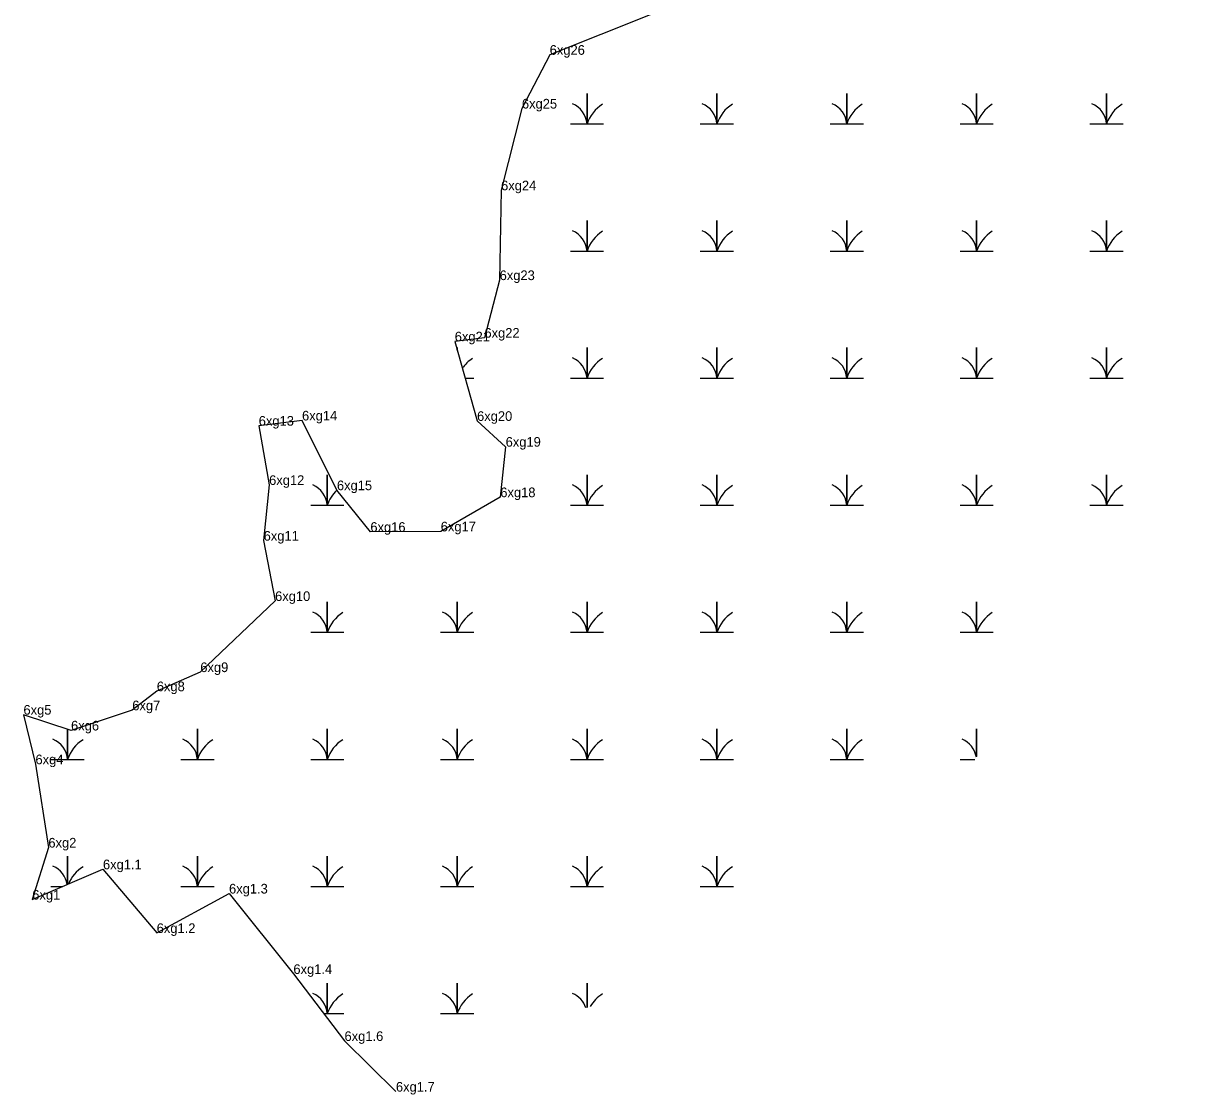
# Model space of a CAD drawing. Extents: x 2072529 to 2268796, y 436423 to 470406.
# Drawn here: x 2152740 to 2153347, y 437861 to 438415 of the extents above; entities that cross this region are included whole.
import ezdxf

# ---------------------------------------------------------------- set-up
doc = ezdxf.new("R2010")
doc.units = 0
for name, color, linetype in [('Exist Environmental Wetland Boundary Cogo Comment', 7, 'Continuous'), ('Exist Environmental Wetland Boundary Cogo Point CELL', 7, 'Continuous'), ('Old_Level_20', 7, 'Continuous')]:
    doc.layers.add(name, color=color, linetype=linetype)

msp = doc.modelspace()

# ---------------------------------------------------------------- linework, layer by layer
at = {"layer": 'Exist Environmental Wetland Boundary Cogo Point CELL'}
for points in [[(2153023.06, 438363.23), (2153031.66, 438363.23), (2153031.66, 438379.01), (2153031.66, 438363.23), (2153040.26, 438363.23)], [(2153090.31, 438363.23), (2153098.91, 438363.23), (2153098.91, 438379.01), (2153098.91, 438363.23), (2153107.51, 438363.23)], [(2153157.56, 438363.23), (2153166.16, 438363.23), (2153166.16, 438379.01), (2153166.16, 438363.23), (2153174.76, 438363.23)], [(2153224.81, 438363.23), (2153233.41, 438363.23), (2153233.41, 438379.01), (2153233.41, 438363.23), (2153242.01, 438363.23)], [(2153292.06, 438363.23), (2153300.66, 438363.23), (2153300.66, 438379.01), (2153300.66, 438363.23), (2153309.26, 438363.23)], [(2153023.06, 438297.43), (2153031.66, 438297.43), (2153031.66, 438313.21), (2153031.66, 438297.43), (2153040.26, 438297.43)], [(2153090.31, 438297.43), (2153098.91, 438297.43), (2153098.91, 438313.21), (2153098.91, 438297.43), (2153107.51, 438297.43)], [(2153157.56, 438297.43), (2153166.16, 438297.43), (2153166.16, 438313.21), (2153166.16, 438297.43), (2153174.76, 438297.43)], [(2153224.81, 438297.43), (2153233.41, 438297.43), (2153233.41, 438313.21), (2153233.41, 438297.43), (2153242.01, 438297.43)], [(2153292.06, 438297.43), (2153300.66, 438297.43), (2153300.66, 438313.21), (2153300.66, 438297.43), (2153309.26, 438297.43)], [(2152964.41, 438246.19), (2152964.41, 438247.41), (2152964.41, 438246.19)], [(2153023.06, 438231.63), (2153031.66, 438231.63), (2153031.66, 438247.41), (2153031.66, 438231.63), (2153040.26, 438231.63)], [(2153090.31, 438231.63), (2153098.91, 438231.63), (2153098.91, 438247.41), (2153098.91, 438231.63), (2153107.51, 438231.63)], [(2153157.56, 438231.63), (2153166.16, 438231.63), (2153166.16, 438247.41), (2153166.16, 438231.63), (2153174.76, 438231.63)], [(2153224.81, 438231.63), (2153233.41, 438231.63), (2153233.41, 438247.41), (2153233.41, 438231.63), (2153242.01, 438231.63)], [(2153292.06, 438231.63), (2153300.66, 438231.63), (2153300.66, 438247.41), (2153300.66, 438231.63), (2153309.26, 438231.63)], [(2152968.5, 438231.63), (2152973.01, 438231.63)], [(2152888.56, 438165.83), (2152897.16, 438165.83), (2152897.16, 438181.61), (2152897.16, 438165.83), (2152905.76, 438165.83)], [(2153023.06, 438165.83), (2153031.66, 438165.83), (2153031.66, 438181.61), (2153031.66, 438165.83), (2153040.26, 438165.83)], [(2153090.31, 438165.83), (2153098.91, 438165.83), (2153098.91, 438181.61), (2153098.91, 438165.83), (2153107.51, 438165.83)], [(2153157.56, 438165.83), (2153166.16, 438165.83), (2153166.16, 438181.61), (2153166.16, 438165.83), (2153174.76, 438165.83)], [(2153224.81, 438165.83), (2153233.41, 438165.83), (2153233.41, 438181.61), (2153233.41, 438165.83), (2153242.01, 438165.83)], [(2153292.06, 438165.83), (2153300.66, 438165.83), (2153300.66, 438181.61), (2153300.66, 438165.83), (2153309.26, 438165.83)], [(2152888.56, 438100.03), (2152897.16, 438100.03), (2152897.16, 438115.81), (2152897.16, 438100.03), (2152905.76, 438100.03)], [(2152955.81, 438100.03), (2152964.41, 438100.03), (2152964.41, 438115.81), (2152964.41, 438100.03), (2152973.01, 438100.03)], [(2153023.06, 438100.03), (2153031.66, 438100.03), (2153031.66, 438115.81), (2153031.66, 438100.03), (2153040.26, 438100.03)], [(2153090.31, 438100.03), (2153098.91, 438100.03), (2153098.91, 438115.81), (2153098.91, 438100.03), (2153107.51, 438100.03)], [(2153157.56, 438100.03), (2153166.16, 438100.03), (2153166.16, 438115.81), (2153166.16, 438100.03), (2153174.76, 438100.03)], [(2153224.81, 438100.03), (2153233.41, 438100.03), (2153233.41, 438115.81), (2153233.41, 438100.03), (2153242.01, 438100.03)], [(2152754.06, 438034.23), (2152762.66, 438034.23), (2152762.66, 438049.82)], [(2152762.66, 438049.82), (2152762.66, 438034.23), (2152771.26, 438034.23)], [(2152821.31, 438034.23), (2152829.91, 438034.23), (2152829.91, 438050.01), (2152829.91, 438034.23), (2152838.51, 438034.23)], [(2152888.56, 438034.23), (2152897.16, 438034.23), (2152897.16, 438050.01), (2152897.16, 438034.23), (2152905.76, 438034.23)], [(2152955.81, 438034.23), (2152964.41, 438034.23), (2152964.41, 438050.01), (2152964.41, 438034.23), (2152973.01, 438034.23)], [(2153023.06, 438034.23), (2153031.66, 438034.23), (2153031.66, 438050.01), (2153031.66, 438034.23), (2153040.26, 438034.23)], [(2153090.31, 438034.23), (2153098.91, 438034.23), (2153098.91, 438050.01), (2153098.91, 438034.23), (2153107.51, 438034.23)], [(2153157.56, 438034.23), (2153166.16, 438034.23), (2153166.16, 438050.01), (2153166.16, 438034.23), (2153174.76, 438034.23)], [(2153233.41, 438035.69), (2153233.41, 438050.01), (2153233.41, 438035.69)], [(2153224.81, 438034.23), (2153232.4, 438034.23)], [(2152762.66, 437969.48), (2152762.66, 437984.21), (2152762.66, 437969.48)], [(2152821.31, 437968.43), (2152829.91, 437968.43), (2152829.91, 437984.21), (2152829.91, 437968.43), (2152838.51, 437968.43)], [(2152888.56, 437968.43), (2152897.16, 437968.43), (2152897.16, 437984.21), (2152897.16, 437968.43), (2152905.76, 437968.43)], [(2152955.81, 437968.43), (2152964.41, 437968.43), (2152964.41, 437984.21), (2152964.41, 437968.43), (2152973.01, 437968.43)], [(2153023.06, 437968.43), (2153031.66, 437968.43), (2153031.66, 437984.21), (2153031.66, 437968.43), (2153040.26, 437968.43)], [(2153090.31, 437968.43), (2153098.91, 437968.43), (2153098.91, 437984.21), (2153098.91, 437968.43), (2153107.51, 437968.43)], [(2152754.06, 437968.43), (2152760.19, 437968.43)], [(2152895.28, 437902.63), (2152897.16, 437902.63), (2152897.16, 437918.41), (2152897.16, 437902.63), (2152905.76, 437902.63)], [(2152955.81, 437902.63), (2152964.41, 437902.63), (2152964.41, 437918.41), (2152964.41, 437902.63), (2152973.01, 437902.63)], [(2153031.66, 437905.77), (2153031.66, 437918.41), (2153031.66, 437905.77)]]:
    msp.add_lwpolyline(points, dxfattribs=at)
for centre, radius, start, end in [((2153019.4, 438362.34), 12.3, 4.14034, 67.53497), ((2153086.65, 438362.34), 12.3, 4.14034, 67.53497), ((2153153.9, 438362.34), 12.3, 4.14034, 67.53497), ((2153221.15, 438362.34), 12.3, 4.14034, 67.53497), ((2153288.4, 438362.34), 12.3, 4.14034, 67.53497), ((2153049.9, 438357.16), 19.22, 122.12745, 161.62219), ((2153117.15, 438357.16), 19.22, 122.12745, 161.62219), ((2153184.4, 438357.16), 19.22, 122.12745, 161.62219), ((2153251.65, 438357.16), 19.22, 122.12745, 161.62219), ((2153318.9, 438357.16), 19.22, 122.12745, 161.62219), ((2153019.4, 438296.54), 12.3, 4.14034, 67.53497), ((2153049.9, 438291.36), 19.22, 122.12745, 161.62219), ((2153086.65, 438296.54), 12.3, 4.14034, 67.53497), ((2153117.15, 438291.36), 19.22, 122.12745, 161.62219), ((2153153.9, 438296.54), 12.3, 4.14034, 67.53497), ((2153184.4, 438291.36), 19.22, 122.12745, 161.62219), ((2153221.15, 438296.54), 12.3, 4.14034, 67.53497), ((2153251.65, 438291.36), 19.22, 122.12745, 161.62219), ((2153288.4, 438296.54), 12.3, 4.14034, 67.53497), ((2153318.9, 438291.36), 19.22, 122.12745, 161.62219), ((2152982.65, 438225.56), 19.22, 122.12745, 144.2598), ((2153019.4, 438230.74), 12.3, 4.14034, 67.53497), ((2153049.9, 438225.56), 19.22, 122.12745, 161.62219), ((2153086.65, 438230.74), 12.3, 4.14034, 67.53497), ((2153117.15, 438225.56), 19.22, 122.12745, 161.62219), ((2153153.9, 438230.74), 12.3, 4.14034, 67.53497), ((2153184.4, 438225.56), 19.22, 122.12745, 161.62219), ((2153221.15, 438230.74), 12.3, 4.14034, 67.53497), ((2153251.65, 438225.56), 19.22, 122.12745, 161.62219), ((2153288.4, 438230.74), 12.3, 4.14034, 67.53497), ((2153318.9, 438225.56), 19.22, 122.12745, 161.62219), ((2152884.9, 438164.94), 12.3, 4.14034, 67.53497), ((2152915.4, 438159.76), 19.22, 133.70823, 161.62219), ((2153019.4, 438164.94), 12.3, 4.14034, 67.53497), ((2153049.9, 438159.76), 19.22, 122.12745, 161.62219), ((2153086.65, 438164.94), 12.3, 4.14034, 67.53497), ((2153117.15, 438159.76), 19.22, 122.12745, 161.62219), ((2153153.9, 438164.94), 12.3, 4.14034, 67.53497), ((2153184.4, 438159.76), 19.22, 122.12745, 161.62219), ((2153221.15, 438164.94), 12.3, 4.14034, 67.53497), ((2153251.65, 438159.76), 19.22, 122.12745, 161.62219), ((2153288.4, 438164.94), 12.3, 4.14034, 67.53497), ((2153318.9, 438159.76), 19.22, 122.12745, 161.62219), ((2152884.9, 438099.14), 12.3, 4.14034, 67.53497), ((2152915.4, 438093.96), 19.22, 122.12745, 161.62219), ((2152952.15, 438099.14), 12.3, 4.14034, 67.53497), ((2152982.65, 438093.96), 19.22, 122.12745, 161.62219), ((2153019.4, 438099.14), 12.3, 4.14034, 67.53497), ((2153049.9, 438093.96), 19.22, 122.12745, 161.62219), ((2153086.65, 438099.14), 12.3, 4.14034, 67.53497), ((2153117.15, 438093.96), 19.22, 122.12745, 161.62219), ((2153153.9, 438099.14), 12.3, 4.14034, 67.53497), ((2153184.4, 438093.96), 19.22, 122.12745, 161.62219), ((2153221.15, 438099.14), 12.3, 4.14034, 67.53497), ((2153251.65, 438093.96), 19.22, 122.12745, 161.62219), ((2152750.4, 438033.34), 12.3, 4.14034, 67.53497), ((2152780.9, 438028.16), 19.22, 122.12745, 161.62219), ((2152817.65, 438033.34), 12.3, 4.14034, 67.53497), ((2152848.15, 438028.16), 19.22, 122.12745, 161.62219), ((2152884.9, 438033.34), 12.3, 4.14034, 67.53497), ((2152915.4, 438028.16), 19.22, 122.12745, 161.62219), ((2152952.15, 438033.34), 12.3, 4.14034, 67.53497), ((2152982.65, 438028.16), 19.22, 122.12745, 161.62219), ((2153019.4, 438033.34), 12.3, 4.14034, 67.53497), ((2153049.9, 438028.16), 19.22, 122.12745, 161.62219), ((2153086.65, 438033.34), 12.3, 4.14034, 67.53497), ((2153117.15, 438028.16), 19.22, 122.12745, 161.62219), ((2153153.9, 438033.34), 12.3, 4.14034, 67.53497), ((2153184.4, 438028.16), 19.22, 122.12745, 161.62219), ((2153221.15, 438033.34), 12.3, 9.98599, 67.53497), ((2152750.4, 437967.54), 12.3, 8.87538, 67.53497), ((2152817.65, 437967.54), 12.3, 4.14034, 67.53497), ((2152884.9, 437967.54), 12.3, 4.14034, 67.53497), ((2152952.15, 437967.54), 12.3, 4.14034, 67.53497), ((2153019.4, 437967.54), 12.3, 4.14034, 67.53497), ((2153086.65, 437967.54), 12.3, 4.14034, 67.53497), ((2152780.9, 437962.36), 19.22, 122.12745, 157.61543), ((2152848.15, 437962.36), 19.22, 122.12745, 161.62219), ((2152915.4, 437962.36), 19.22, 122.12745, 161.62219), ((2152982.65, 437962.36), 19.22, 122.12745, 161.62219), ((2153049.9, 437962.36), 19.22, 122.12745, 161.62219), ((2153117.15, 437962.36), 19.22, 122.12745, 161.62219), ((2152884.9, 437901.74), 12.3, 4.14034, 67.53497), ((2152915.4, 437896.56), 19.22, 122.12745, 161.62219), ((2152952.15, 437901.74), 12.3, 4.14034, 67.53497), ((2152982.65, 437896.56), 19.22, 122.12745, 161.62219), ((2153019.4, 437901.74), 12.3, 18.17833, 67.53497), ((2153049.9, 437896.56), 19.22, 122.12745, 149.45681)]:
    msp.add_arc(centre, radius, start, end, dxfattribs=at)
at = {"layer": 'Old_Level_20'}
for p, q in [((2153012.33, 438399.04), (2153012.33, 438399.04)), ((2153012.33, 438399.04), (2153012.33, 438399.04)), ((2152997.95, 438371.2), (2152997.95, 438371.2)), ((2152997.95, 438371.2), (2152997.95, 438371.2)), ((2152987.16, 438328.86), (2152987.16, 438328.86)), ((2152987.16, 438328.86), (2152987.16, 438328.86)), ((2152986.41, 438282.38), (2152986.41, 438282.38)), ((2152978.54, 438252.57), (2152978.54, 438252.57)), ((2152978.54, 438252.57), (2152978.54, 438252.57)), ((2152963.16, 438250.66), (2152963.16, 438250.66)), ((2152963.16, 438250.66), (2152963.16, 438250.66)), ((2152884.09, 438209.7), (2152884.09, 438209.7)), ((2152861.66, 438207.01), (2152861.66, 438207.01)), ((2152974.72, 438209.48), (2152974.72, 438209.48)), ((2152989.52, 438196.13), (2152989.52, 438196.13)), ((2152867.04, 438176.33), (2152867.04, 438176.33)), ((2152902.15, 438173.61), (2152902.15, 438173.61)), ((2152986.75, 438169.99), (2152986.75, 438169.99)), ((2152919.48, 438152.05), (2152919.48, 438152.05)), ((2152955.91, 438152.29), (2152955.91, 438152.29)), ((2152864.21, 438147.49), (2152864.21, 438147.49)), ((2152870.13, 438116.25), (2152870.13, 438116.25)), ((2152831.41, 438079.45), (2152831.41, 438079.45)), ((2152808.88, 438069.54), (2152808.88, 438069.54)), ((2152796.18, 438059.67), (2152796.18, 438059.67)), ((2152739.84, 438057.4), (2152739.84, 438057.4)), ((2152764.48, 438049.22), (2152764.48, 438049.22)), ((2152746.06, 438031.73), (2152746.06, 438031.73)), ((2152752.74, 437988.6), (2152752.74, 437988.6)), ((2152781.01, 437977.36), (2152781.01, 437977.36)), ((2152744.41, 437961.65), (2152744.41, 437961.65)), ((2152846.29, 437964.8), (2152846.29, 437964.8)), ((2152808.82, 437944.37), (2152808.82, 437944.37)), ((2152879.62, 437923.16), (2152879.62, 437923.16)), ((2152906.08, 437888.47), (2152906.08, 437888.47)), ((2152932.71, 437862.24), (2152932.71, 437862.24))]:
    msp.add_line(p, q, dxfattribs=at)
for points in [[(2153367.2, 438544.18), (2153242.69, 438491.33), (2153154.34, 438456.74), (2153091.7, 438430.78), (2153012.33, 438399.04), (2152997.95, 438371.2), (2152987.16, 438328.86), (2152986.41, 438282.38), (2152978.54, 438252.57), (2152963.16, 438250.66)], [(2152963.16, 438250.66), (2152974.72, 438209.48), (2152989.52, 438196.13), (2152986.75, 438169.99), (2152955.91, 438152.29), (2152919.48, 438152.05), (2152902.15, 438173.61), (2152884.09, 438209.7), (2152861.66, 438207.01), (2152867.04, 438176.33), (2152864.21, 438147.49), (2152870.13, 438116.25), (2152831.41, 438079.45), (2152808.88, 438069.54), (2152796.18, 438059.67), (2152764.48, 438049.22), (2152739.84, 438057.4), (2152746.06, 438031.73), (2152752.74, 437988.6), (2152744.41, 437961.65)], [(2152744.41, 437961.65), (2152781.01, 437977.36), (2152808.82, 437944.37), (2152846.29, 437964.8), (2152879.62, 437923.16), (2152906.08, 437888.47), (2152932.71, 437862.24)]]:
    msp.add_lwpolyline(points, dxfattribs=at)

# ---------------------------------------------------------------- texts
at = {"layer": 'Exist Environmental Wetland Boundary Cogo Comment'}
for s, p in [('6xg26', (2153012.33, 438399.04)), ('6xg25', (2152997.95, 438371.2)), ('6xg24', (2152987.16, 438328.86)), ('6xg23', (2152986.41, 438282.38)), ('6xg21', (2152963.16, 438250.66)), ('6xg22', (2152978.54, 438252.57)), ('6xg13', (2152861.66, 438207.01)), ('6xg14', (2152884.09, 438209.7)), ('6xg20', (2152974.72, 438209.48)), ('6xg19', (2152989.52, 438196.13)), ('6xg12', (2152867.04, 438176.33)), ('6xg15', (2152902.15, 438173.61)), ('6xg18', (2152986.75, 438169.99)), ('6xg16', (2152919.48, 438152.05)), ('6xg17', (2152955.91, 438152.29)), ('6xg11', (2152864.21, 438147.49)), ('6xg10', (2152870.13, 438116.25)), ('6xg9', (2152831.41, 438079.45)), ('6xg8', (2152808.88, 438069.54)), ('6xg7', (2152796.18, 438059.67)), ('6xg5', (2152739.84, 438057.4)), ('6xg6', (2152764.48, 438049.22)), ('6xg4', (2152746.06, 438031.73)), ('6xg2', (2152752.74, 437988.6)), ('6xg1.1', (2152781.01, 437977.36)), ('6xg1', (2152744.41, 437961.65)), ('6xg1.3', (2152846.29, 437964.8)), ('6xg1.2', (2152808.82, 437944.37)), ('6xg1.4', (2152879.62, 437923.16)), ('6xg1.6', (2152906.08, 437888.47)), ('6xg1.7', (2152932.71, 437862.24))]:
    msp.add_text(s, height=5, dxfattribs=at).set_placement(p)

doc.saveas('drawing.dxf')
